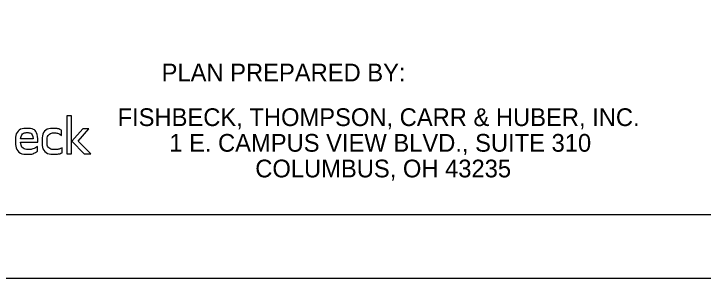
# Model space of a CAD drawing. Extents: x 0 to 34, y 0 to 22.
# Drawn here: x 2.94 to 8.38, y 0 to 2.09 of the extents above; entities that cross this region are included whole.
import ezdxf

# ---------------------------------------------------------------- set-up
doc = ezdxf.new("R2010")
doc.units = 0
for name, color, linetype in [('SH_Border', 7, 'Continuous'), ('SH_Cut_Line', 7, 'Continuous'), ('SH_Data', 7, 'Continuous'), ('SH_Text', 7, 'Continuous')]:
    doc.layers.add(name, color=color, linetype=linetype)

msp = doc.modelspace()

# ---------------------------------------------------------------- linework, layer by layer
at = {"layer": 'SH_Cut_Line'}
for p, q in [((3.3951, 1.28), (3.3562, 1.28)), ((3.3562, 1.28), (3.3562, 0.9821)), ((3.3951, 0.9821), (3.3951, 1.28)), ((3.3154, 1.1271), (3.3154, 1.1686)), ((3.4838, 1.1782), (3.3968, 1.0821)), ((3.4462, 1.0821), (3.5301, 1.1782)), ((3.5301, 1.1782), (3.4838, 1.1782)), ((3.0908, 1.1001), (2.992, 1.1001)), ((2.9912, 1.0743), (3.1292, 1.0743)), ((3.1257, 1.0013), (3.1257, 1.0389)), ((3.3968, 1.0821), (3.4951, 0.9821)), ((3.5476, 0.9821), (3.4462, 1.0821)), ((3.3198, 0.9895), (3.3198, 1.028)), ((3.3562, 0.9821), (3.3951, 0.9821)), ((3.4951, 0.9821), (3.5476, 0.9821))]:
    msp.add_line(p, q, dxfattribs=at)
for points in [[(3.1292, 1.0743), (3.1292, 1.1468), (3.096, 1.1822), (3.044, 1.1822), (2.9899, 1.1822), (2.9523, 1.142), (2.9523, 1.0826), (2.9523, 1.0284), (2.9864, 0.9782), (3.0475, 0.9782), (3.0807, 0.9782), (3.1021, 0.9856), (3.1257, 1.0013)], [(2.992, 1.1001), (2.9973, 1.1311), (3.0152, 1.1485), (3.0449, 1.1485), (3.0724, 1.1485), (3.0895, 1.1298), (3.0908, 1.1001)], [(3.3154, 1.1686), (3.2966, 1.1769), (3.2813, 1.1822), (3.2586, 1.1822), (3.1992, 1.1822), (3.1616, 1.1411), (3.1616, 1.0765), (3.1616, 1.0188), (3.2027, 0.9782), (3.2612, 0.9782), (3.2818, 0.9782), (3.3067, 0.9834), (3.3198, 0.9895)], [(3.3198, 1.028), (3.3001, 1.0192), (3.2844, 1.0149), (3.2678, 1.0149), (3.2276, 1.0149), (3.2014, 1.0393), (3.2014, 1.08), (3.2014, 1.1197), (3.2259, 1.1464), (3.2612, 1.1464), (3.2783, 1.1464), (3.2931, 1.142), (3.3154, 1.1271)], [(3.1257, 1.0389), (3.103, 1.024), (3.0807, 1.0153), (3.0571, 1.0153), (3.0196, 1.0153), (2.9973, 1.0354), (2.9912, 1.0743)]]:
    msp.add_open_spline(points, degree=3, dxfattribs=at)
at = {"layer": 'SH_Data'}
msp.add_lwpolyline([(1.5, 21.5), (33.5, 21.5), (33.5, 0.5), (1.5, 0.5)], close=True, dxfattribs=at)
at = {"layer": 'SH_Text'}
msp.add_lwpolyline([(0, 0), (34, 0), (34, 22), (0, 22)], close=True, dxfattribs=at)

# ---------------------------------------------------------------- texts
at = {"layer": 'SH_Border'}
for s, p in [('PLAN PREPARED BY:', (4.1053, 1.553)), ('FISHBECK, THOMPSON, CARR & HUBER, INC.', (3.7579, 1.2006)), ('1 E. CAMPUS VIEW BLVD., SUITE 310', (4.1655, 0.9981)), ('COLUMBUS, OH 43235', (4.8443, 0.7956))]:
    msp.add_text(s, height=0.14, dxfattribs=at).set_placement(p)

doc.saveas('drawing.dxf')
